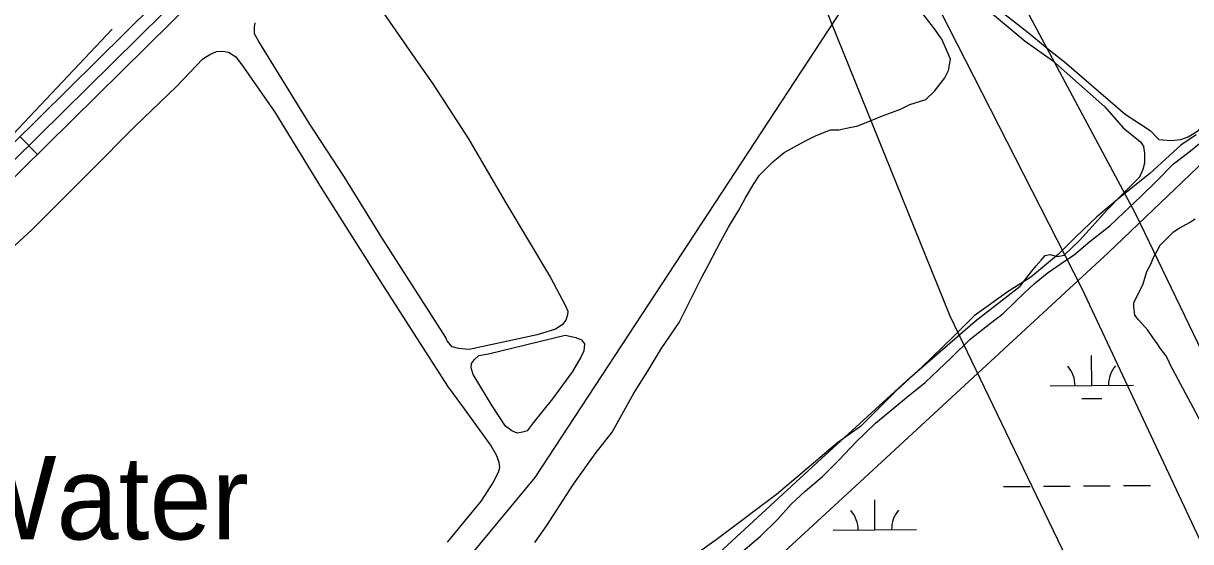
# Model space of a CAD drawing. Extents: x 3568792 to 3606828, y 529143 to 554785.
# Drawn here: x 3579503 to 3580902, y 543866 to 544488 of the extents above; entities that cross this region are included whole.
import ezdxf

# ---------------------------------------------------------------- set-up
doc = ezdxf.new("R2010")
doc.units = 0
for name, color, linetype in [('V-RIVR-IDEN', 7, 'Continuous'), ('V-ROAD-CNTR', 7, 'Continuous'), ('V-SITE-OTLN', 7, 'Continuous'), ('V-SITE-VEGE', 7, 'Continuous'), ('V-TOPO-SHOR', 7, 'Continuous'), ('V-UTIL-LINE', 7, 'Continuous'), ('V-WETL-SWMP', 7, 'Continuous')]:
    doc.layers.add(name, color=color, linetype=linetype)

msp = doc.modelspace()

# ---------------------------------------------------------------- linework, layer by layer
at = {"layer": 'V-ROAD-CNTR'}
msp.add_line((3579520.1, 544330.5), (3579499.1, 544351.9), dxfattribs=at)
for points in [[(3579392.9, 545366.8), (3579509.9, 545252.8), (3579629.9, 545137), (3579736, 545026.5), (3579826.7, 544931.9), (3579871.7, 544880.6), (3579885.4, 544862.7), (3579892.3, 544848.8), (3579897.9, 544832.1), (3579898.4, 544812.9), (3579898.8, 544800.7), (3579898.8, 544783.4), (3579898.2, 544770.2), (3579896.6, 544761.3), (3579894.6, 544746.7), (3579891.1, 544737.2), (3579882.8, 544716.3), (3579841.8, 544671.2), (3579670.7, 544500), (3579430.6, 544263.3)], [(3579655.6, 545088.5), (3579725.2, 545016.1), (3579815.7, 544921.7), (3579860.1, 544871.1), (3579872.6, 544854.7), (3579878.4, 544843.1), (3579883, 544829.4), (3579883.5, 544812.4), (3579883.8, 544800.5), (3579883.8, 544783.7), (3579883.3, 544771.9), (3579881.8, 544763.6), (3579880, 544750.3), (3579877.1, 544742.6), (3579869.9, 544724.4), (3579831, 544681.5), (3579660.1, 544510.7), (3579420.3, 544274.2)], [(3579782.9, 544999.2), (3579837.8, 544942), (3579883.4, 544890.1), (3579898.2, 544870.7), (3579906.2, 544854.6), (3579912.9, 544834.7), (3579913.4, 544813.4), (3579913.8, 544800.9), (3579913.8, 544783), (3579913.1, 544768.5), (3579911.4, 544758.9), (3579909.3, 544743), (3579905.1, 544731.8), (3579895.7, 544708.3), (3579852.7, 544660.8), (3579681.3, 544489.4), (3579440.9, 544252.4)]]:
    msp.add_lwpolyline(points, dxfattribs=at)
at = {"layer": 'V-SITE-OTLN'}
msp.add_lwpolyline([(3579384.2, 545786.4), (3579538.3, 545657), (3579549.8, 545647.4), (3580635.2, 544735.3), (3580116.2, 543943), (3579501.6, 543200.6), (3579362.7, 543061.6), (3579330.4, 543039.8), (3578532.2, 542499.2), (3578292.2, 542336.7), (3578519.2, 542033.8), (3578546.1, 541997.9), (3577753.6, 541531.3), (3577722.7, 541563.5), (3577444.5, 541854.1), (3577305.5, 541999.2), (3577161, 542150.2), (3577019.9, 542441.1), (3576823.4, 542760.8)], dxfattribs=at)
at = {"layer": 'V-SITE-VEGE'}
for points in [[(3580480.7, 544359.9), (3580495.4, 544363.3), (3580502.2, 544364.5), (3580519.2, 544371.3), (3580532.8, 544376.9), (3580554.3, 544384.9), (3580565.6, 544390.5), (3580584.9, 544396.2), (3580595.1, 544406.4), (3580607.5, 544422.2), (3580612, 544431.3), (3580614.3, 544444.9), (3580612, 544450.5), (3580604.1, 544468.6), (3580595.1, 544481.1), (3580580.3, 544500.3)], [(3580116.1, 543865.2), (3580130.8, 543885.6), (3580150, 543916.2), (3580162.5, 543935.4), (3580188.5, 543971.6), (3580208.9, 543997.7), (3580235, 544044.1), (3580252, 544071.3), (3580267.8, 544097.3), (3580289.3, 544129), (3580316.5, 544183.3), (3580324.4, 544198.1), (3580339.2, 544226.4), (3580348.2, 544243.3), (3580360.7, 544263.7), (3580368.6, 544278.4), (3580378.8, 544295.4), (3580385.6, 544305.6), (3580401.4, 544321.5), (3580415, 544332.8), (3580439.9, 544346.4), (3580453.5, 544353.2), (3580470.5, 544360), (3580480.7, 544359.9)], [(3580908.7, 544354.2), (3580890.6, 544341.8), (3580877, 544329.3), (3580853.2, 544307.8), (3580817, 544278.4), (3580789.8, 544255.7), (3580764.9, 544232), (3580743.4, 544210.5), (3580710.5, 544183.3), (3580683.3, 544166.3), (3580642.6, 544136.9), (3580617.7, 544112), (3580580.3, 544075.7), (3580549.7, 544047.4), (3580506.7, 544004.4), (3580479.5, 543985.2), (3580434.2, 543946.7), (3580405.9, 543922.9), (3580333.4, 543868.6), (3580292.7, 543839.1)], [(3580939.2, 543963.6), (3580878.1, 544078), (3580875.8, 544083.6), (3580872.4, 544089.3), (3580865.6, 544098.4), (3580861.1, 544105.2), (3580857.7, 544109.7), (3580850.9, 544119.9), (3580839.6, 544132.3), (3580835.1, 544138), (3580833.9, 544148.2), (3580833.9, 544152.7), (3580845.3, 544175.4), (3580849.8, 544190.1), (3580854.3, 544199.1), (3580857.7, 544207.1), (3580862.2, 544215), (3580865.6, 544221.8), (3580881.5, 544237.6), (3580888.3, 544242.1), (3580900.7, 544248.9), (3580907.5, 544253.5)]]:
    msp.add_lwpolyline(points, dxfattribs=at)
at = {"layer": 'V-TOPO-SHOR'}
for points in [[(3580586.8, 544553), (3580586.8, 544559.9), (3580587.2, 544560.4), (3580590, 544561.8), (3580595, 544561.8), (3580662, 544512.2), (3580707.3, 544476.5), (3580734.8, 544454.5), (3580750.9, 544441.6), (3580823.8, 544378.8), (3580853.6, 544359.1)], [(3580586.8, 544553), (3580664.7, 544498.9), (3580703.7, 544466.4), (3580736.7, 544443), (3580799.5, 544387.5), (3580821.5, 544362.3), (3580842.1, 544345.8), (3580846.2, 544339.8)], [(3579925.3, 544513.8), (3579976, 544440.8), (3579994.1, 544415), (3580036.7, 544349.3), (3580080.2, 544274.6), (3580135, 544183.1), (3580153.1, 544149.1), (3580155.8, 544142.7), (3580155.4, 544138.2), (3580153.5, 544131.9), (3580149, 544126.4), (3580140.9, 544121), (3580119.1, 544114.2), (3580037.6, 544096.6), (3580024.9, 544097.9), (3580017.2, 544099.7), (3580010.8, 544107.4), (3580009.5, 544111.1)], [(3580009.5, 544111.1), (3579933.4, 544230.2), (3579888.1, 544303.2), (3579845.6, 544367.9), (3579785.3, 544465.8), (3579780.3, 544474.9), (3579780.3, 544483), (3579781.2, 544488.4)], [(3579609.8, 544480.5), (3579484.3, 544347.8), (3579417.7, 544288), (3579356.1, 544236.3)], [(3579445.5, 544177.8), (3579513.9, 544240.7), (3579583.3, 544310), (3579636.7, 544363.9), (3579687, 544412.4), (3579718.3, 544445), (3579726.9, 544450.4), (3579734.6, 544454), (3579742.3, 544454.5), (3579749.1, 544453.1), (3579757.7, 544447.7), (3579767.2, 544435), (3579804.8, 544381.1), (3579860, 544290.5), (3579931.6, 544177.2), (3580011.7, 544052.6), (3580028.5, 544030), (3580063.8, 543980.6), (3580069.7, 543970.2), (3580072.9, 543961.6), (3580073.8, 543954.8), (3580072.4, 543949.3), (3580066.1, 543937.6), (3580052, 543915.4), (3580011.3, 543865.5)], [(3580853.6, 544359.1), (3580864.2, 544348.6), (3580878.9, 544347.2), (3580890.4, 544348.5), (3580899.1, 544351.8), (3580911.5, 544359.1), (3580928.5, 544379.8), (3580959.3, 544412.9), (3580967.6, 544422.6), (3580980.5, 544435.4), (3580994.4, 544447.2)], [(3580350, 543841.5), (3580386.8, 543872.8), (3580407, 543893), (3580423.6, 543911.4), (3580440.2, 543927), (3580460.8, 543944.5), (3580481.1, 543964.2), (3580500.9, 543985.4), (3580524.3, 544008.4), (3580561.6, 544039.2), (3580584.1, 544057.1), (3580615.4, 544087), (3580637.9, 544109), (3580662.3, 544128.3), (3580677.4, 544139.8), (3580692.2, 544154.1), (3580703.2, 544164.7), (3580714.7, 544175.2), (3580730.3, 544188.1), (3580746.9, 544199.6), (3580763, 544210.6), (3580781.4, 544226.3), (3580805.3, 544245.1), (3580822.3, 544260.7), (3580842.5, 544280), (3580861.8, 544298.9), (3580881.6, 544319.1), (3580900, 544333.4), (3580916.6, 544346.7)], [(3580337.1, 543853), (3580459.9, 543966.1), (3580565.7, 544062.6), (3580643.9, 544130.7), (3580697.7, 544172.5), (3580711.5, 544190), (3580717, 544196.8), (3580723, 544203.7), (3580728, 544209.3), (3580733.6, 544210.6), (3580742.7, 544208.3), (3580750.6, 544209.7), (3580769.4, 544227.6), (3580802.5, 544264.4), (3580818.2, 544280.5), (3580841.2, 544303.5), (3580845.3, 544312.7), (3580847.1, 544320.5), (3580847.1, 544332), (3580846.2, 544339.8)], [(3580042.5, 544066.7), (3580039.8, 544074.8), (3580040.3, 544079.8), (3580043.9, 544084.8), (3580049.3, 544089.3), (3580060.7, 544091.6), (3580152.6, 544113.8), (3580165.3, 544111), (3580172.1, 544108.3), (3580175.7, 544103.3), (3580174.8, 544095.2), (3580171.2, 544087.5), (3580161.2, 544070.3), (3580137.2, 544037.7), (3580114.1, 544008.7), (3580106.9, 543999.2), (3580101.4, 543997.4), (3580095.1, 543996.4), (3580088.7, 543999.2), (3580081, 544004.6), (3580065.2, 544029.1), (3580042.5, 544066.7)]]:
    msp.add_lwpolyline(points, dxfattribs=at)
at = {"layer": 'V-UTIL-LINE'}
for points in [[(3576104.5, 549614.5), (3575980.6, 549380.7), (3575975.6, 549330), (3575795.7, 548982.2), (3575847, 548939.3), (3577996.3, 547114.3), (3577969.6, 547146.5), (3578424.4, 546757.6), (3580608.2, 544894.2), (3580586.2, 544823.9), (3580566.4, 544763.8), (3580836, 544259.4), (3581735.4, 542392.7), (3581735.4, 542392), (3583243.9, 539198.6), (3583455.7, 538592.3), (3583631, 538180.4), (3585262.9, 534651)], [(3585128.3, 534649.8), (3583719.6, 537704.2), (3582542.5, 540395.5), (3580772.2, 544169.5), (3580472.7, 544757.3), (3580549.2, 544846), (3580609.1, 544913.1), (3580567.4, 544989.1), (3578476.1, 546727.5), (3578101.5, 547060.9), (3578033.8, 547070), (3577965.7, 547126.4), (3576392.6, 548421.7), (3576369.9, 548541.5), (3575884.2, 548880.3), (3575580.1, 549146.9), (3575181.4, 549483.6), (3575183.4, 549530.1)], [(3577710.9, 547207.8), (3579113.1, 546060.5), (3580033.9, 545289.5), (3580171.2, 545147), (3580456.9, 544524.8), (3580613.7, 544136.9)], [(3580613.7, 544136.9), (3580964.8, 543407.4), (3581516.1, 542211), (3581921.3, 541354.1), (3582238.9, 540665.3), (3582616.2, 539901), (3582941.5, 539167.7), (3583265.6, 538481.9), (3583288.7, 538443.2), (3583363.9, 538253.6), (3583745.1, 537485.2), (3584083.5, 536767.4), (3584210.8, 536519), (3584467.6, 535947.4)]]:
    msp.add_lwpolyline(points, dxfattribs=at)
at = {"layer": 'V-WETL-SWMP'}
for p, q in [((3580783.8, 544053.3), (3580783.5, 544089.3)), ((3580733.8, 544052.9), (3580833.8, 544053.7)), ((3580771.9, 544037.8), (3580795.9, 544038)), ((3580677.9, 543932.4), (3580709.9, 543932.6)), ((3580725.9, 543932.8), (3580757.9, 543933)), ((3580773.9, 543933.2), (3580805.9, 543933.4)), ((3580821.9, 543933.6), (3580853.9, 543933.8)), ((3580523.8, 543880.3), (3580523.5, 543916.3)), ((3580473.8, 543879.9), (3580573.8, 543880.7))]:
    msp.add_line(p, q, dxfattribs=at)
msp.add_lwpolyline([(3579889.6, 542221.4), (3579765.7, 542510.2), (3579567.2, 542914.8), (3579518, 543003.2), (3579511.6, 543021.4), (3579516.2, 543030.5), (3579779.5, 543268.2), (3580204.1, 543659.9), (3580484.8, 543918.6), (3580803.7, 544212.8), (3581026, 544425.1)], dxfattribs=at)
for centre, start, end in [((3580728.5, 544053.3), 359.7115, 41.2552), ((3580839, 544054.3), 139.7115, 181.2552), ((3580468.5, 543880.3), 359.7115, 41.2552), ((3580579, 543881.2), 139.7115, 181.2552)]:
    msp.add_arc(centre, 35.2, start, end, dxfattribs=at)

# ---------------------------------------------------------------- texts
at = {"layer": 'V-RIVR-IDEN'}
msp.add_text('Water', height=100, dxfattribs=at).set_placement((3579416.7, 543869))

doc.saveas('drawing.dxf')
